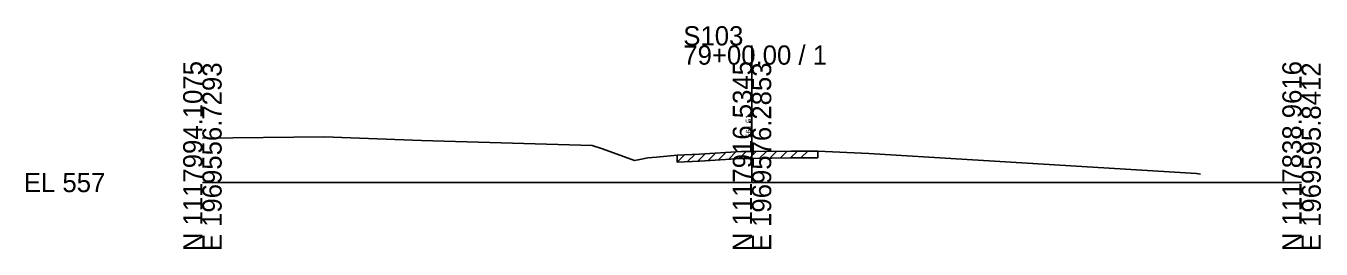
# Model space of a CAD drawing. Extents: x -26 to 163, y -10 to 45020.
# Drawn here: x -25.7 to 162.8, y 37990.3 to 38022.8 of the extents above; entities that cross this region are included whole.
import ezdxf

# ---------------------------------------------------------------- set-up
doc = ezdxf.new("R2010")
doc.units = 0
for name, color, linetype in [('RD_GPK_XS_Cell', 7, 'Continuous'), ('RD_XS_ExGround', 7, 'Continuous'), ('RD_XS_ExPaveRet', 7, 'Continuous'), ('RD_XS_TX_Elev_EX', 7, 'Continuous')]:
    doc.layers.add(name, color=color, linetype=linetype)

msp = doc.modelspace()

# ---------------------------------------------------------------- linework, layer by layer
at = {"layer": 'RD_GPK_XS_Cell'}
for p, q in [((80, 38000), (80, 38019.96)), ((0, 38000), (80, 38000)), ((80, 38000), (160, 38000))]:
    msp.add_line(p, q, dxfattribs=at)
at = {"layer": 'RD_XS_ExGround'}
for p, q in [((0, 38006.44), (17.73, 38006.65)), ((17.73, 38006.65), (31.9, 38006.12)), ((31.9, 38006.12), (56.75, 38005.4)), ((56.75, 38005.4), (58.26, 38004.9)), ((58.26, 38004.9), (62.92, 38003.23)), ((72.35, 38004.13), (78.4, 38004.5)), ((78.4, 38004.5), (80, 38004.51)), ((80, 38004.51), (85.7, 38004.58)), ((85.7, 38004.58), (89.59, 38004.58)), ((89.59, 38004.58), (96.99, 38004.25)), ((62.92, 38003.23), (63.68, 38003.34)), ((63.68, 38003.34), (64.83, 38003.61)), ((64.83, 38003.61), (66.11, 38003.71)), ((66.11, 38003.71), (69.1, 38003.96)), ((69.1, 38003.96), (72.35, 38004.13)), ((96.99, 38004.25), (111.33, 38003.33)), ((111.33, 38003.33), (144.7, 38001.31)), ((144.7, 38001.31), (145.27, 38001.21))]:
    msp.add_line(p, q, dxfattribs=at)
at = {"layer": 'RD_XS_ExPaveRet'}
for p, q in [((76.61, 38003.39), (77.67, 38004.45)), ((78.11, 38003.48), (79.13, 38004.5)), ((79.61, 38003.51), (80.62, 38004.52)), ((81.11, 38003.53), (82.12, 38004.54)), ((82.61, 38003.54), (83.62, 38004.56)), ((84.11, 38003.56), (85.12, 38004.57)), ((85.61, 38003.58), (86.61, 38004.58)), ((87.11, 38003.58), (88.11, 38004.58)), ((89.59, 38004.58), (89.59, 38003.58)), ((69.1, 38002.96), (70.16, 38004.02)), ((69.1, 38002.96), (69.1, 38003.96)), ((69.1, 38002.96), (72.35, 38003.13)), ((70.6, 38003.04), (71.66, 38004.09)), ((72.1, 38003.11), (73.17, 38004.18)), ((72.35, 38003.13), (78.4, 38003.5)), ((73.6, 38003.2), (74.67, 38004.27)), ((75.11, 38003.3), (76.17, 38004.36)), ((78.4, 38003.5), (80, 38003.51)), ((80, 38003.51), (85.7, 38003.58)), ((85.7, 38003.58), (89.59, 38003.58))]:
    msp.add_line(p, q, dxfattribs=at)

# ---------------------------------------------------------------- texts
at = {"layer": 'RD_GPK_XS_Cell'}
for s, p in [('S103', (70, 38019.96)), ('79+00.00 / 1', (70, 38017.16)), ('EL 557', (-26, 37998.6))]:
    msp.add_text(s, height=2.8, dxfattribs=at).set_placement(p)
for s, p in [('N 1117994.1075', (0, 37990)), ('E 1969556.7293', (2.8, 37990)), ('N 1117916.5345', (80, 37990)), ('E 1969576.2853', (82.8, 37990)), ('N 1117838.9616', (160, 37990)), ('E 1969595.8412', (162.8, 37990))]:
    msp.add_text(s, height=2.8, rotation=90, dxfattribs=at).set_placement(p)
at = {"layer": 'RD_XS_TX_Elev_EX'}
msp.add_text('561.51', height=0.8, rotation=90, dxfattribs=at).set_placement((79.9, 38006.51))

doc.saveas('drawing.dxf')
